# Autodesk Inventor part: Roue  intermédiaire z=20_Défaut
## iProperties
Shininess: 64.0
Length Units: 11269
Angle Units: 11279
Time Units: 11290
Mass Units: 11283
Length Display Precision: 3
Angle Display Precision: 2
Compacted: True
Part Number: Roue  intermédiaire z=20_Défaut
Document SubType Name: Modeling
Created: 2006-01
Material: Par défaut
Designer: riri
Density: 0.0
Volumn: 0.0
Area: 0.0
PropertySet Name: Model Information
Control State: 0
Master: False
Checked Out: False
Author: riri
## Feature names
1. Base1
